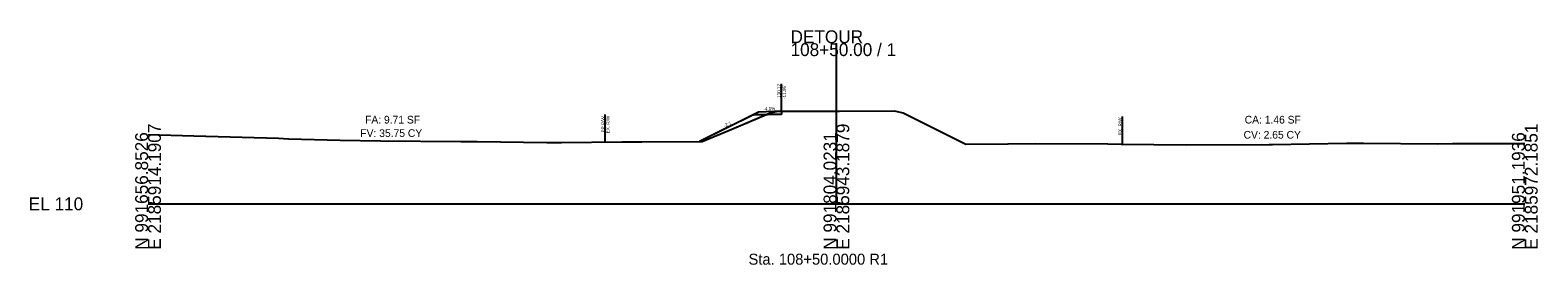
# Model space of a CAD drawing. Extents: x -3604 to 2303, y -13 to 9543.
# Drawn here: x 1974.3 to 2302.8, y 2486.7 to 2537.8 of the extents above; entities that cross this region are included whole.
import ezdxf

# ---------------------------------------------------------------- set-up
doc = ezdxf.new("R2010")
doc.units = 0
for name, color, linetype in [('Draft_XS_Grid', 7, 'Continuous'), ('Draft_XS_Text', 7, 'Continuous'), ('DTM_X_GROUND', 7, 'Continuous'), ('ROW_TX', 7, 'Continuous'), ('XS_CELL', 7, 'Continuous'), ('XS_M_SHAPES_EARTHWORK', 7, 'Continuous'), ('XS_P_ASPHALT', 7, 'Continuous'), ('XS_P_GROUND', 7, 'Continuous'), ('XS_P_TX_CLEARZONE', 7, 'Continuous'), ('XS_P_TX_FS_BS', 7, 'Continuous'), ('XS_SHEET_EW_TX_AREA', 7, 'Continuous'), ('XS_SHEET_EW_TX_VOLUME', 7, 'Continuous'), ('XS_X_ROW', 7, 'Continuous')]:
    doc.layers.add(name, color=color, linetype=linetype)

msp = doc.modelspace()

# ---------------------------------------------------------------- linework, layer by layer
at = {"layer": 'DTM_X_GROUND'}
msp.add_lwpolyline([(2000, 2515.1), (2009.94, 2514.8), (2028.45, 2514.32), (2030.6, 2514.15), (2041.83, 2513.89), (2050.64, 2513.71), (2068.14, 2513.57), (2071.68, 2513.56), (2086.89, 2513.36), (2090.12, 2513.39), (2103.22, 2513.54), (2103.96, 2513.54), (2107.57, 2513.54), (2120.73, 2513.56), (2127.18, 2516.27), (2135.59, 2519.85), (2136.18, 2519.96), (2137.32, 2520.17), (2149.05, 2520.21), (2149.91, 2520.22), (2150.7, 2520.22), (2162.62, 2520.25), (2164.46, 2519.82), (2164.56, 2519.8), (2165.28, 2519.45), (2168.49, 2517.85), (2178.23, 2513.01), (2187.34, 2513.05), (2187.45, 2513.05), (2193.37, 2513.13), (2209.12, 2513.06), (2212.02, 2513), (2226.26, 2512.83), (2244.3, 2512.94), (2245, 2512.94), (2261.12, 2513.2), (2264.88, 2513.24), (2281.02, 2513.11), (2284.26, 2513.15), (2300, 2513.15)], dxfattribs=at)
msp.add_lwpolyline([(2000, 2515.1), (2009.94, 2514.8), (2028.45, 2514.32), (2030.6, 2514.15), (2041.83, 2513.89), (2050.64, 2513.71), (2068.14, 2513.57), (2071.68, 2513.56), (2086.89, 2513.36), (2090.12, 2513.39), (2103.22, 2513.54), (2103.96, 2513.54), (2107.57, 2513.54), (2120.73, 2513.56), (2127.18, 2516.27), (2135.59, 2519.85), (2136.18, 2519.96), (2137.32, 2520.17), (2149.05, 2520.21), (2149.91, 2520.22), (2150.7, 2520.22), (2162.62, 2520.25), (2164.46, 2519.82), (2164.56, 2519.8), (2165.28, 2519.45), (2168.49, 2517.85), (2178.23, 2513.01), (2187.34, 2513.05), (2187.45, 2513.05), (2193.37, 2513.13), (2209.12, 2513.06), (2212.02, 2513), (2226.26, 2512.83), (2244.3, 2512.94), (2245, 2512.94), (2261.12, 2513.2), (2264.88, 2513.24), (2281.02, 2513.11), (2284.26, 2513.15), (2300, 2513.15)], dxfattribs=at)
at = {"layer": 'ROW_TX'}
msp.add_line((2099.64, 2513.5), (2099.64, 2519.5), dxfattribs=at)
at = {"layer": 'XS_CELL'}
for p, q in [((2150, 2500), (2150, 2535)), ((2000, 2500), (2150, 2500)), ((2150, 2500), (2300, 2500))]:
    msp.add_line(p, q, dxfattribs=at)
at = {"layer": 'XS_M_SHAPES_EARTHWORK'}
for points in [[(2134.73, 2519.48), (2135.59, 2519.85), (2136.18, 2519.96), (2137.32, 2520.17), (2138.05, 2520.17), (2138.05, 2519.55), (2138, 2519.55)], [(2120.18, 2513.56), (2120.73, 2513.56), (2127.18, 2516.27), (2134.73, 2519.48), (2131.91, 2519.42)]]:
    msp.add_lwpolyline(points, close=True, dxfattribs=at)
at = {"layer": 'XS_P_ASPHALT'}
for points in [[(2138, 2520.17), (2138, 2519.55)], [(2138.05, 2520.17), (2138, 2520.17)], [(2138.05, 2520.17), (2138.05, 2519.55)], [(2131.91, 2519.42), (2138, 2519.55)], [(2138, 2519.55), (2138.05, 2519.55)]]:
    msp.add_lwpolyline(points, dxfattribs=at)
at = {"layer": 'XS_P_GROUND'}
for points in [[(2133, 2519.97), (2120.18, 2513.56)], [(2138, 2520.17), (2133, 2519.97)]]:
    msp.add_lwpolyline(points, dxfattribs=at)
at = {"layer": 'XS_P_TX_CLEARZONE'}
msp.add_line((2138.05, 2520.17), (2138.05, 2526.17), dxfattribs=at)
at = {"layer": 'XS_X_ROW'}
msp.add_line((2212.3, 2513.01), (2212.3, 2519.01), dxfattribs=at)

# ---------------------------------------------------------------- texts
at = {"layer": 'Draft_XS_Grid'}
msp.add_text('-', height=0.0001, dxfattribs=at).set_placement((2000, 2500))
at = {"layer": 'Draft_XS_Text'}
msp.add_text('Sta. 108+50.0000 R1', height=2.4, dxfattribs=at).set_placement((2130.84, 2486.75))
at = {"layer": 'ROW_TX'}
msp.add_text('PP R/W', height=0.72, rotation=90, dxfattribs=at).set_placement((2099.49, 2515.54))
at = {"layer": 'XS_CELL'}
for s, p in [('DETOUR', (2140, 2535)), ('108+50.00 / 1', (2140, 2532.2)), ('EL 110', (1974, 2498.6))]:
    msp.add_text(s, height=2.8, dxfattribs=at).set_placement(p)
for s, p in [('E 2185914.1907', (2002.8, 2490)), ('E 2185943.1879', (2152.8, 2490)), ('E 2185972.1851', (2302.8, 2490)), ('N 991656.8526', (2000, 2490)), ('N 991804.0231', (2150, 2490)), ('N 991951.1936', (2300, 2490))]:
    msp.add_text(s, height=2.8, rotation=90, dxfattribs=at).set_placement(p)
at = {"layer": 'XS_P_ASPHALT'}
for p in [(2137.96, 2520.11), (2138.01, 2520.11), (2131.87, 2519.36), (2137.96, 2519.49), (2138.01, 2519.49)]:
    msp.add_text('X', height=0.12, dxfattribs=at).set_placement(p)
at = {"layer": 'XS_P_GROUND'}
msp.add_text('X', height=0.12, dxfattribs=at).set_placement((2120.14, 2513.5))
at = {"layer": 'XS_P_TX_CLEARZONE'}
for s, p in [('130.17', (2137.81, 2523.1)), ("-11.95'", (2139.01, 2522.86))]:
    msp.add_text(s, height=0.72, rotation=90, dxfattribs=at).set_placement(p)
at = {"layer": 'XS_P_TX_FS_BS'}
for s, rotation, p in [('-4.0%', 2.2906, (2134.09, 2520.32)), ('-2:1', 26.5651, (2125.64, 2516.63))]:
    msp.add_text(s, height=0.72, rotation=rotation, dxfattribs=at).set_placement(p)
at = {"layer": 'XS_SHEET_EW_TX_AREA'}
for s, p in [('FA: 9.71 SF', (2047.29, 2517.5)), ('CA: 1.46 SF', (2238.96, 2517.5))]:
    msp.add_text(s, height=1.68, dxfattribs=at).set_placement(p)
at = {"layer": 'XS_SHEET_EW_TX_VOLUME'}
for s, p in [('FV: 35.75 CY', (2046.25, 2514.57)), ('CV: 2.65 CY', (2238.72, 2514.21))]:
    msp.add_text(s, height=1.68, dxfattribs=at).set_placement(p)
at = {"layer": 'XS_X_ROW'}
for p in [(2100.57, 2515.38), (2212.16, 2514.99)]:
    msp.add_text('EX. R/W', height=0.72, rotation=90, dxfattribs=at).set_placement(p)

doc.saveas('drawing.dxf')
